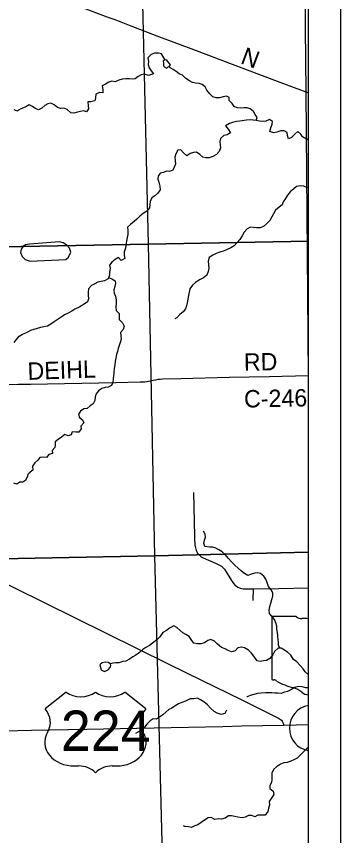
# Model space of a CAD drawing. Extents: x 0 to 34, y 0 to 22.
# Drawn here: x 8.833 to 9.895, y 17.274 to 19.953 of the extents above; entities that cross this region are included whole.
import ezdxf

# ---------------------------------------------------------------- set-up
doc = ezdxf.new("R2010")
doc.units = 0
for name, color, linetype in [('GM_X_Corporation', 7, 'Continuous'), ('GM_X_Corporation_Text', 7, 'Continuous'), ('GM_X_County_Road', 7, 'Continuous'), ('GM_X_County_Road_Text', 7, 'Continuous'), ('GM_X_Minor_Lake', 7, 'Continuous'), ('GM_X_Minor_River', 7, 'Continuous'), ('GM_X_State_Location', 7, 'Continuous'), ('GM_X_State_Route', 7, 'Continuous'), ('GM_X_Township_Road', 7, 'Continuous'), ('GM_X_Unincorporated', 7, 'Continuous'), ('GM_X_US_Location', 7, 'Continuous'), ('GM_X_US_Route', 7, 'Continuous'), ('GM_X_US_Shield', 7, 'Continuous'), ('SH_Data', 7, 'Continuous')]:
    doc.layers.add(name, color=color, linetype=linetype)

msp = doc.modelspace()

# ---------------------------------------------------------------- linework, layer by layer
at = {"layer": 'GM_X_Corporation'}
msp.add_lwpolyline([(9.7895, 15.1275), (9.7895, 20.2375), (9.7789, 20.2374), (8.9707, 20.221), (8.4324, 20.2139), (8.2231, 20.2112), (7.2254, 20.198), (7.2266, 20.122), (7.2291, 20.0061), (7.2317, 19.8848), (7.2344, 19.7492), (7.237, 19.6097), (7.2392, 19.4543), (7.2426, 19.2998), (7.2468, 19.0896), (7.2467, 19.0557), (7.2751, 17.5764), (7.2764, 17.5202), (7.2799, 17.4174), (7.283, 17.3071), (7.2872, 17.1772)], dxfattribs=at)
for points in [[(9.7895, 19.2182), (9.7895, 20.2353), (9.7215, 20.2341), (9.2406, 20.2272), (9.2644, 19.2076)], [(9.2406, 20.2272), (9.2644, 19.2076), (8.2571, 19.1893), (8.2335, 20.2135), (8.7368, 20.2215)], [(9.7895, 18.2006), (9.7895, 19.2182), (9.2644, 19.2076), (9.2853, 18.1891)], [(8.2571, 19.1893), (9.2644, 19.2076), (9.2853, 18.1891), (8.2786, 18.1687)], [(9.7895, 17.178), (9.7895, 18.2006), (9.2853, 18.1891), (9.3117, 17.1675)], [(9.2853, 18.1891), (9.3117, 17.1675), (8.3006, 17.1406), (8.2786, 18.1687)]]:
    msp.add_lwpolyline(points, close=True, dxfattribs=at)
at = {"layer": 'GM_X_Corporation_Text'}
for p, q in [((9.669, 17.9864), (9.669, 17.7863)), ((9.7488, 17.9899), (9.6715, 17.9899)), ((9.7895, 17.7338), (9.7895, 17.9831))]:
    msp.add_line(p, q, dxfattribs=at)
for centre, radius, start, end in [((9.672, 17.9868), 0.00305, 98.978, 188.5967), ((9.7672, 18.0131), 0.0296, 231.6404, 271.1117), ((9.777, 17.8775), 0.1064, 83.2659, 94.9883), ((9.672, 17.7859), 0.00308, 171.4911, 258.3065), ((9.6725, 17.8063), 0.0235, 267.339, 280.6039), ((9.6773, 17.7748), 0.00848, 29.7484, 93.2717), ((9.7844, 17.9546), 0.2019, 240.4129, 257.1985), ((9.7242, 17.6964), 0.0632, 47.1842, 75.836), ((9.7925, 17.7738), 0.0401, 230.7004, 265.6796)]:
    msp.add_arc(centre, radius, start, end, dxfattribs=at)
at = {"layer": 'GM_X_County_Road'}
msp.add_line((9.7895, 19.7017), (9.7813, 19.7048), dxfattribs=at)
for points in [[(9.7813, 19.7048), (9.6794, 19.7439), (9.5401, 19.7962), (9.4229, 19.8402), (9.2939, 19.8885), (9.2088, 19.9214), (9.1764, 19.9337), (9.1527, 19.9429), (9.1303, 19.951), (9.0241, 19.991)], [(9.7895, 18.7775), (9.6608, 18.7743), (9.5299, 18.7715), (9.3713, 18.7678), (9.3125, 18.7662), (9.3035, 18.7659), (9.2958, 18.765), (9.2882, 18.7637), (9.2811, 18.7624), (9.2719, 18.7602), (9.2658, 18.7587), (9.2599, 18.7575), (9.2537, 18.7569), (9.2457, 18.7567), (9.2378, 18.7565), (9.1588, 18.755), (8.8795, 18.7495), (8.8402, 18.7488), (8.8039, 18.7481)], [(8.2622, 18.3652), (8.3616, 18.3152), (8.5946, 18.1992), (8.8266, 18.0841), (8.9262, 18.0351), (9.125, 17.9371), (9.33, 17.8357), (9.4415, 17.781), (9.5684, 17.7185), (9.6907, 17.6578)], [(9.6907, 17.6578), (9.6943, 17.656), (9.6978, 17.6539), (9.7009, 17.651), (9.703, 17.6479), (9.7051, 17.6439), (9.709, 17.6354)]]:
    msp.add_lwpolyline(points, dxfattribs=at)
at = {"layer": 'GM_X_Minor_Lake'}
for points in [[(9.3374, 19.795), (9.3242, 19.8115), (9.3174, 19.8095), (9.3133, 19.8076), (9.3142, 19.7989), (9.3146, 19.7909), (9.32, 19.786), (9.3254, 19.7842)], [(9.3254, 19.7842), (9.3374, 19.795)], [(9.7895, 19.5566), (9.7895, 19.5566), (9.7869, 19.5531), (9.7881, 19.5474), (9.7895, 19.5467)], [(8.8754, 19.2086), (8.863, 19.2054), (8.8551, 19.2004), (8.8484, 19.192), (8.8463, 19.1805), (8.8521, 19.1673), (8.8621, 19.158), (8.8781, 19.1521), (8.995, 19.1582), (9.004, 19.1656), (9.0109, 19.182), (9.007, 19.1948), (8.9985, 19.205), (8.9859, 19.2128), (8.9737, 19.2153)], [(8.9737, 19.2153), (8.8754, 19.2086)], [(9.1415, 17.8343), (9.1342, 17.8399), (9.1236, 17.8406), (9.1134, 17.8385), (9.1059, 17.832), (9.1106, 17.8157), (9.1217, 17.8109), (9.1334, 17.816), (9.1394, 17.824), (9.1419, 17.8305)], [(9.1419, 17.8305), (9.1415, 17.8343)]]:
    msp.add_lwpolyline(points, dxfattribs=at)
at = {"layer": 'GM_X_Minor_River'}
for points in [[(9.32, 19.8103), (9.3084, 19.8307), (9.2978, 19.8329), (9.2856, 19.8327), (9.2743, 19.8284), (9.2634, 19.8176), (9.2655, 19.807), (9.2645, 19.7952), (9.2677, 19.7846), (9.2739, 19.7748), (9.2823, 19.765), (9.2649, 19.7599), (9.2516, 19.7639), (9.2414, 19.7623), (9.2312, 19.7564), (9.2214, 19.7483), (9.212, 19.7475), (9.2017, 19.7492), (9.1911, 19.7487), (9.1793, 19.7478), (9.168, 19.7443), (9.1559, 19.7392), (9.1456, 19.7413), (9.1354, 19.7374), (9.1249, 19.7312), (9.1139, 19.7254), (9.1156, 19.7144), (9.1154, 19.7033), (9.1047, 19.7044), (9.0926, 19.6989), (9.0917, 19.6871), (9.0899, 19.6768), (9.0763, 19.6732), (9.0668, 19.6735), (9.0681, 19.661), (9.0694, 19.6507), (9.0623, 19.6408), (9.0527, 19.6445), (9.0429, 19.6421), (9.0331, 19.64), (9.0213, 19.6361), (9.0107, 19.6375), (8.9995, 19.6487), (8.9877, 19.6532), (8.9775, 19.6515), (8.9672, 19.6548), (8.9565, 19.6642), (8.9458, 19.6694), (8.9359, 19.6673), (8.9261, 19.6619), (8.9164, 19.653), (8.905, 19.6476), (8.8947, 19.6513), (8.8852, 19.6587), (8.8748, 19.6643), (8.8639, 19.657), (8.8455, 19.6491)], [(9.6182, 19.6123), (9.6209, 19.6221), (9.6143, 19.6327), (9.6092, 19.6425), (9.5981, 19.6507), (9.5886, 19.654), (9.5787, 19.6543), (9.5662, 19.653), (9.5559, 19.6536), (9.546, 19.6585), (9.5394, 19.6683), (9.5298, 19.678), (9.5301, 19.6879), (9.5205, 19.692), (9.5095, 19.6895), (9.4982, 19.6867), (9.4868, 19.6862), (9.4765, 19.6899), (9.4661, 19.6993), (9.4569, 19.7117), (9.4507, 19.7223), (9.4407, 19.7305), (9.4312, 19.7338), (9.4198, 19.7344), (9.4095, 19.7366), (9.3995, 19.7418), (9.3873, 19.7496), (9.3769, 19.7605), (9.3662, 19.7649), (9.3563, 19.7724), (9.3467, 19.7795), (9.3367, 19.7847), (9.3306, 19.7889)], [(8.8246, 19.6481), (8.8353, 19.6444), (8.8455, 19.6491)], [(9.7878, 19.5486), (9.7701, 19.5586), (9.7639, 19.5684), (9.7543, 19.5763), (9.7442, 19.5674), (9.7341, 19.5566), (9.7242, 19.5523), (9.7203, 19.5633), (9.7194, 19.5736), (9.7095, 19.5788), (9.6988, 19.579), (9.686, 19.5739), (9.6758, 19.5727), (9.6632, 19.5767), (9.6661, 19.5881), (9.6709, 19.6003), (9.6711, 19.6098), (9.6616, 19.6162), (9.6491, 19.6107), (9.6392, 19.6094), (9.629, 19.6101), (9.6187, 19.6122), (9.6084, 19.6136), (9.5989, 19.6143), (9.5861, 19.6134), (9.5648, 19.6108), (9.5539, 19.6088), (9.5406, 19.6056), (9.5304, 19.6028), (9.518, 19.5954), (9.5265, 19.5841), (9.5334, 19.5724), (9.5229, 19.5662), (9.5119, 19.5631), (9.5007, 19.5542), (9.4993, 19.5439), (9.5002, 19.5333), (9.5011, 19.523), (9.497, 19.5112), (9.4877, 19.5016), (9.4756, 19.4946), (9.4643, 19.491), (9.4537, 19.4905), (9.443, 19.4931), (9.433, 19.5017), (9.4223, 19.5091), (9.4124, 19.5079), (9.4019, 19.5043), (9.3909, 19.4974), (9.3798, 19.5063), (9.371, 19.5165), (9.3615, 19.5156), (9.3552, 19.5038), (9.3519, 19.4931), (9.3528, 19.4813), (9.3533, 19.4699), (9.3497, 19.4604), (9.3452, 19.4497), (9.3343, 19.4461), (9.3248, 19.4472), (9.3146, 19.4425), (9.3032, 19.4404), (9.2969, 19.4305), (9.2959, 19.421), (9.2994, 19.4104), (9.3026, 19.3983), (9.3032, 19.3861), (9.2961, 19.3746), (9.2863, 19.3662), (9.2766, 19.3592), (9.2706, 19.3473), (9.27, 19.3378), (9.269, 19.3272), (9.2604, 19.3164), (9.2476, 19.3087), (9.2375, 19.2998), (9.2277, 19.2902), (9.218, 19.2821), (9.2067, 19.2721), (9.1966, 19.2632), (9.1982, 19.2526), (9.1976, 19.2397), (9.1951, 19.2302), (9.193, 19.2184), (9.1916, 19.205), (9.1902, 19.1955), (9.1862, 19.1829), (9.1856, 19.1712), (9.1876, 19.1609), (9.1763, 19.1547), (9.1667, 19.1641), (9.1565, 19.1579), (9.1449, 19.149), (9.1374, 19.1394), (9.1395, 19.1284), (9.1381, 19.1166), (9.1378, 19.1067), (9.1334, 19.0949), (9.1214, 19.0887), (9.11, 19.0863), (9.0998, 19.0842)], [(9.7895, 19.3938), (9.7859, 19.3928), (9.7737, 19.3976), (9.763, 19.3989), (9.7505, 19.3969), (9.7408, 19.3896), (9.7295, 19.3795), (9.7205, 19.3684), (9.7142, 19.3577), (9.7068, 19.347), (9.7027, 19.3363), (9.693, 19.3286), (9.6813, 19.3189), (9.6743, 19.3074), (9.6695, 19.2971), (9.6628, 19.2853), (9.6523, 19.2745), (9.6418, 19.266), (9.6316, 19.2617), (9.6194, 19.2616), (9.6095, 19.2629), (9.5997, 19.2636), (9.588, 19.2581), (9.5786, 19.2478), (9.5716, 19.2355), (9.5649, 19.2233), (9.5454, 19.2025), (9.5352, 19.1963), (9.5235, 19.1912), (9.5137, 19.1862), (9.4994, 19.1822), (9.4869, 19.1771), (9.4763, 19.1724), (9.4639, 19.1647), (9.4606, 19.1525), (9.4623, 19.1403), (9.4625, 19.1289), (9.4607, 19.1183), (9.4567, 19.1072), (9.4458, 19.0983), (9.4326, 19.091), (9.4198, 19.0832), (9.4093, 19.074), (9.4011, 19.0617), (9.3986, 19.0506), (9.396, 19.04), (9.3939, 19.0278), (9.3922, 19.016), (9.3896, 19.0065), (9.3863, 18.9969), (9.3789, 18.9866), (9.368, 18.9777), (9.3586, 18.9673), (9.3519, 18.9634)], [(9.0998, 19.0842), (9.09, 19.0784), (9.0791, 19.0726), (9.069, 19.0622), (9.0676, 19.0515), (9.0677, 19.0413), (9.069, 19.0288), (9.0653, 19.0192), (9.0544, 19.0119), (9.0405, 19.003), (9.0246, 18.9952), (9.0145, 18.9886), (9.002, 18.9827), (8.99, 18.9765), (8.9798, 18.9695), (8.9666, 18.9606), (8.9561, 18.9544), (8.9456, 18.9463), (8.9346, 18.9401), (8.9229, 18.9381), (8.9115, 18.9357), (8.9013, 18.9325), (8.8904, 18.9293), (8.8794, 18.9258), (8.8709, 18.9215), (8.8692, 18.9202)], [(9.135, 19.0991), (9.1452, 19.095), (9.1559, 19.0887), (9.1576, 19.0792), (9.1554, 19.0693), (9.1521, 19.0587), (9.1526, 19.048), (9.1573, 19.0378), (9.1601, 19.0265), (9.1595, 19.0139), (9.1589, 19.0017), (9.1594, 18.9907), (9.169, 18.9817), (9.1692, 18.9719), (9.1697, 18.9616), (9.1801, 18.9511), (9.1859, 18.9398), (9.1826, 18.9295), (9.174, 18.9191), (9.1745, 18.9096), (9.1762, 18.8979), (9.1722, 18.8864), (9.1656, 18.8669), (9.1634, 18.8574), (9.1605, 18.8471), (9.1588, 18.8357), (9.1566, 18.8258), (9.1552, 18.814), (9.1527, 18.8014), (9.1514, 18.7889), (9.1508, 18.7771), (9.1494, 18.7676), (9.1484, 18.7569), (9.1443, 18.7462), (9.1338, 18.7408), (9.1239, 18.7395), (9.1122, 18.7364), (9.1017, 18.7282), (9.0942, 18.7187), (9.0913, 18.7091), (9.0896, 18.6966), (9.0844, 18.6862), (9.0746, 18.6793), (9.0641, 18.6704), (9.0539, 18.6691), (9.0433, 18.6622), (9.0362, 18.6526), (9.0394, 18.6412), (9.0494, 18.6338), (9.0537, 18.6239), (9.0443, 18.6132), (9.0448, 18.6037), (9.037, 18.5937), (9.0271, 18.5932), (9.0157, 18.5942), (9.012, 18.5843), (9.0022, 18.5811), (8.9915, 18.5859), (8.9806, 18.5771), (8.9693, 18.5697), (8.9596, 18.5616), (8.9601, 18.5521), (8.9591, 18.5426), (8.9504, 18.533), (8.9506, 18.5231), (8.9388, 18.5207), (8.9314, 18.5104), (8.9196, 18.511), (8.9101, 18.5109), (8.9034, 18.5013), (8.8933, 18.4924), (8.8854, 18.4817), (8.8863, 18.4695), (8.8781, 18.4626)], [(8.8261, 18.8868), (8.8336, 18.8964), (8.8415, 18.9074), (8.8529, 18.9136), (8.8642, 18.9183), (8.8692, 18.9202)], [(8.8233, 18.4276), (8.834, 18.4239), (8.8442, 18.4308), (8.8545, 18.4305), (8.8643, 18.4371), (8.8688, 18.4477), (8.8725, 18.458), (8.8781, 18.4626)], [(9.696, 17.8865), (9.6915, 17.8961), (9.6913, 17.906), (9.6901, 17.9155), (9.6888, 17.9265), (9.6879, 17.9375), (9.6855, 17.9489), (9.6857, 17.9587), (9.6822, 17.9697), (9.6775, 17.9803), (9.6621, 18.0006), (9.66, 18.0116), (9.6622, 18.0227), (9.6658, 18.0337), (9.6698, 18.0456), (9.6724, 18.0566), (9.6726, 18.0676), (9.6668, 18.0778), (9.6587, 18.0884), (9.6551, 18.0982), (9.6492, 18.1129), (9.6427, 18.1227), (9.6327, 18.1314), (9.6232, 18.1331), (9.6133, 18.1323), (9.6012, 18.1287), (9.591, 18.1248), (9.5799, 18.1315), (9.57, 18.1389), (9.5592, 18.1487), (9.5489, 18.1577), (9.5377, 18.1693), (9.5277, 18.1806), (9.5165, 18.193), (9.5069, 18.202), (9.4962, 18.2083), (9.4855, 18.2139), (9.476, 18.2172), (9.4665, 18.2171), (9.4501, 18.2188), (9.4466, 18.2294), (9.4484, 18.2404), (9.4516, 18.25), (9.4512, 18.2595), (9.4457, 18.2697)], [(9.7895, 17.7997), (9.7895, 17.7997), (9.7787, 17.809), (9.7718, 17.8188), (9.7633, 17.8286), (9.7506, 17.8425), (9.7406, 17.8496), (9.7314, 17.8636), (9.7214, 17.8725), (9.7106, 17.8808), (9.7003, 17.8863), (9.6905, 17.8866), (9.6785, 17.8754), (9.6721, 17.8651), (9.6632, 17.8528), (9.6522, 17.8466), (9.6424, 17.845), (9.6307, 17.8433), (9.6208, 17.8459), (9.6107, 17.8602), (9.6026, 17.8703), (9.5926, 17.8805), (9.5796, 17.8879), (9.5701, 17.8897), (9.5576, 17.888), (9.5494, 17.8784), (9.5376, 17.8749), (9.5262, 17.8797), (9.5166, 17.8845), (9.5041, 17.8885), (9.4914, 17.9001), (9.4814, 17.9095), (9.4696, 17.9155), (9.4597, 17.9115), (9.4488, 17.9046), (9.4367, 17.9014), (9.4261, 17.9012), (9.4143, 17.9034), (9.4047, 17.9147), (9.3985, 17.9248), (9.3881, 17.9316), (9.3782, 17.9368), (9.3678, 17.9457), (9.3582, 17.954), (9.3483, 17.9599), (9.3347, 17.9522), (9.3242, 17.9445), (9.3125, 17.9375), (9.3024, 17.9244), (9.2923, 17.9144), (9.2788, 17.9036), (9.269, 17.8959), (9.257, 17.8889), (9.2468, 17.8823), (9.2355, 17.8727), (9.2243, 17.8642), (9.2145, 17.858), (9.2036, 17.8507), (9.1915, 17.8448), (9.1809, 17.8435), (9.1684, 17.8388), (9.1585, 17.8387), (9.1487, 17.8378), (9.1405, 17.8351)], [(9.7895, 17.7574), (9.7805, 17.757), (9.7691, 17.7603), (9.7558, 17.7613), (9.7445, 17.7577), (9.7313, 17.7507), (9.7211, 17.7449), (9.7105, 17.7425), (9.7003, 17.7389), (9.6885, 17.7392), (9.679, 17.7398), (9.6692, 17.7408), (9.6597, 17.7407), (9.6487, 17.741), (9.6342, 17.74), (9.6225, 17.738), (9.61, 17.7355), (9.5979, 17.732), (9.5881, 17.7277), (9.5877, 17.7273)], [(9.5211, 17.6836), (9.5151, 17.6736), (9.503, 17.6697), (9.4905, 17.6737), (9.4801, 17.6796), (9.4682, 17.6901), (9.4582, 17.701), (9.4467, 17.7108), (9.4356, 17.7182), (9.4257, 17.7238), (9.4143, 17.7214), (9.4022, 17.7209), (9.3871, 17.7138), (9.375, 17.7091), (9.3633, 17.7048), (9.3531, 17.6978), (9.3422, 17.6901), (9.3324, 17.6866), (9.3121, 17.6688), (9.3016, 17.6607), (9.2918, 17.6549), (9.2812, 17.6556), (9.2706, 17.6493), (9.2605, 17.6386), (9.2527, 17.6282), (9.2407, 17.6178), (9.2305, 17.6124), (9.2226, 17.6073)], [(9.7895, 17.5642), (9.7823, 17.5576), (9.7711, 17.546), (9.7621, 17.5364), (9.7523, 17.5275), (9.7414, 17.5213), (9.7316, 17.5167), (9.7191, 17.5131), (9.7089, 17.5118), (9.6972, 17.5079), (9.6844, 17.499), (9.6746, 17.4897), (9.6698, 17.4775), (9.6696, 17.4661), (9.6693, 17.4566), (9.6679, 17.4471), (9.6631, 17.4376), (9.6629, 17.4273), (9.674, 17.4191), (9.6756, 17.4085), (9.6697, 17.3981), (9.6608, 17.3851), (9.662, 17.3737), (9.6588, 17.3634), (9.6559, 17.3524), (9.6473, 17.3409), (9.6347, 17.3411), (9.6238, 17.3402), (9.6139, 17.3351), (9.6033, 17.3399), (9.5934, 17.3398), (9.5817, 17.3344), (9.5719, 17.3323), (9.5582, 17.3337), (9.5479, 17.3358), (9.5372, 17.3384), (9.527, 17.3386), (9.5168, 17.3309), (9.5047, 17.327), (9.4948, 17.3291), (9.4831, 17.3267), (9.4709, 17.333), (9.4603, 17.3314), (9.449, 17.3248), (9.4381, 17.317), (9.4272, 17.3085), (9.417, 17.3054), (9.406, 17.2999), (9.3961, 17.3025), (9.3843, 17.3031), (9.3798, 17.3053)]]:
    msp.add_lwpolyline(points, dxfattribs=at)
at = {"layer": 'GM_X_State_Route'}
msp.add_lwpolyline([(9.7895, 18.7757), (9.7895, 18.7775), (9.7813, 19.7048), (9.7799, 19.9155), (9.7791, 20.2369), (9.7678, 20.7398)], dxfattribs=at)
at = {"layer": 'GM_X_Township_Road'}
msp.add_line((9.6077, 18.0431), (9.609, 18.0806), dxfattribs=at)
msp.add_lwpolyline([(9.4124, 18.3956), (9.4156, 18.2534), (9.4162, 18.2392), (9.4167, 18.231), (9.4172, 18.2246), (9.4179, 18.2191), (9.4188, 18.2147), (9.4201, 18.2107), (9.4218, 18.2064), (9.4237, 18.2018), (9.4264, 18.1975), (9.4295, 18.1939), (9.433, 18.1901), (9.4382, 18.1859), (9.4439, 18.1824), (9.4873, 18.1635), (9.4958, 18.1597), (9.5005, 18.1573), (9.5044, 18.1546), (9.508, 18.1518), (9.5114, 18.1486), (9.5143, 18.1455), (9.5375, 18.1079), (9.5416, 18.1016), (9.5458, 18.0962), (9.5496, 18.092), (9.5535, 18.0891), (9.5583, 18.0862), (9.5631, 18.0841), (9.5698, 18.0822), (9.5758, 18.0812), (9.5821, 18.0808), (9.589, 18.0806), (9.5955, 18.0805), (9.6015, 18.0805), (9.609, 18.0806), (9.6927, 18.0823), (9.7895, 18.084)], dxfattribs=at)
at = {"layer": 'GM_X_Unincorporated'}
msp.add_line((9.7895, 17.5518), (9.7895, 17.6988), dxfattribs=at)
msp.add_arc((9.8011, 17.6253), 0.0744, 98.9778, 261.0222, dxfattribs=at)
at = {"layer": 'GM_X_US_Route'}
for points in [[(7.2753, 17.5759), (7.283, 17.5754), (7.2928, 17.5748), (7.3048, 17.5746), (7.3702, 17.5757), (8.0334, 17.5908), (8.103, 17.5934), (8.1689, 17.5958), (8.2357, 17.5984), (8.2793, 17.6002), (8.3755, 17.6043), (8.5151, 17.6096), (8.5512, 17.6107), (8.6255, 17.6127), (8.6955, 17.6142), (8.7458, 17.6157), (8.8825, 17.6184), (9.0631, 17.6217), (9.2275, 17.6247), (9.3965, 17.6284), (9.5092, 17.6309)], [(9.5092, 17.6309), (9.5711, 17.6323), (9.709, 17.6354), (9.7895, 17.637)]]:
    msp.add_lwpolyline(points, dxfattribs=at)
at = {"layer": 'GM_X_US_Shield'}
for p, q in [((8.9955, 17.7433), (8.9269, 17.6883)), ((9.2565, 17.6883), (9.1878, 17.7433)), ((9.023, 17.5016), (9.0367, 17.5016)), ((9.1466, 17.5016), (9.1603, 17.5016))]:
    msp.add_line(p, q, dxfattribs=at)
for centre, major_axis, start_param, end_param in [((9.0436, 17.7825), (-0.0687, 0), 0.795399, 2.346194), ((9.1397, 17.7825), (-0.0687, 0), 0.795399, 2.346194), ((8.8481, 17.6442), (0.0961, 0), 5.838949, 6.894067), ((9.3352, 17.6442), (-0.0961, 0), 5.672304, 6.727422), ((9.0219, 17.5785), (0.0961, 0), 2.702327, 4.723529), ((9.1614, 17.5785), (-0.0961, 0), 1.559657, 3.580859), ((9.0367, 17.4466), (-0.0687, 0), 3.785094, 4.712389), ((9.1466, 17.4466), (-0.0687, 0), 4.712389, 5.639684)]:
    msp.add_ellipse(centre, major_axis=major_axis, ratio=0.8, start_param=start_param, end_param=end_param, dxfattribs=at)
at = {"layer": 'SH_Data'}
msp.add_line((9.8945, 20.8873), (9.8945, 13.8873), dxfattribs=at)

# ---------------------------------------------------------------- texts
at = {"layer": 'GM_X_County_Road_Text'}
for s, height, rotation, p in [('N', 0.0568, 339.444, (9.5638, 19.8006)), ('RD', 0.05682, 0.9872, (9.5781, 18.794)), ('DEIHL', 0.05682, 2.0615, (8.8702, 18.764)), ('C-246', 0.05682, 1.1011, (9.5787, 18.6736))]:
    msp.add_text(s, height=height, rotation=rotation, dxfattribs=at).set_placement(p)
at = {"layer": 'GM_X_State_Location'}
msp.add_text('45', height=0.000189, rotation=0, dxfattribs=at).set_placement((9.7502, 17.8593))
at = {"layer": 'GM_X_US_Location'}
for s in ['0', '/']:
    msp.add_text(s, height=0.000189, dxfattribs=at).set_placement((9.0918, 17.6168))
msp.add_text('224', height=0.000189, rotation=0, dxfattribs=at).set_placement((9.0335, 17.5776))
at = {"layer": 'GM_X_US_Shield'}
msp.add_text('224', height=0.13184, dxfattribs=at).set_placement((8.9785, 17.551))

doc.saveas('drawing.dxf')
